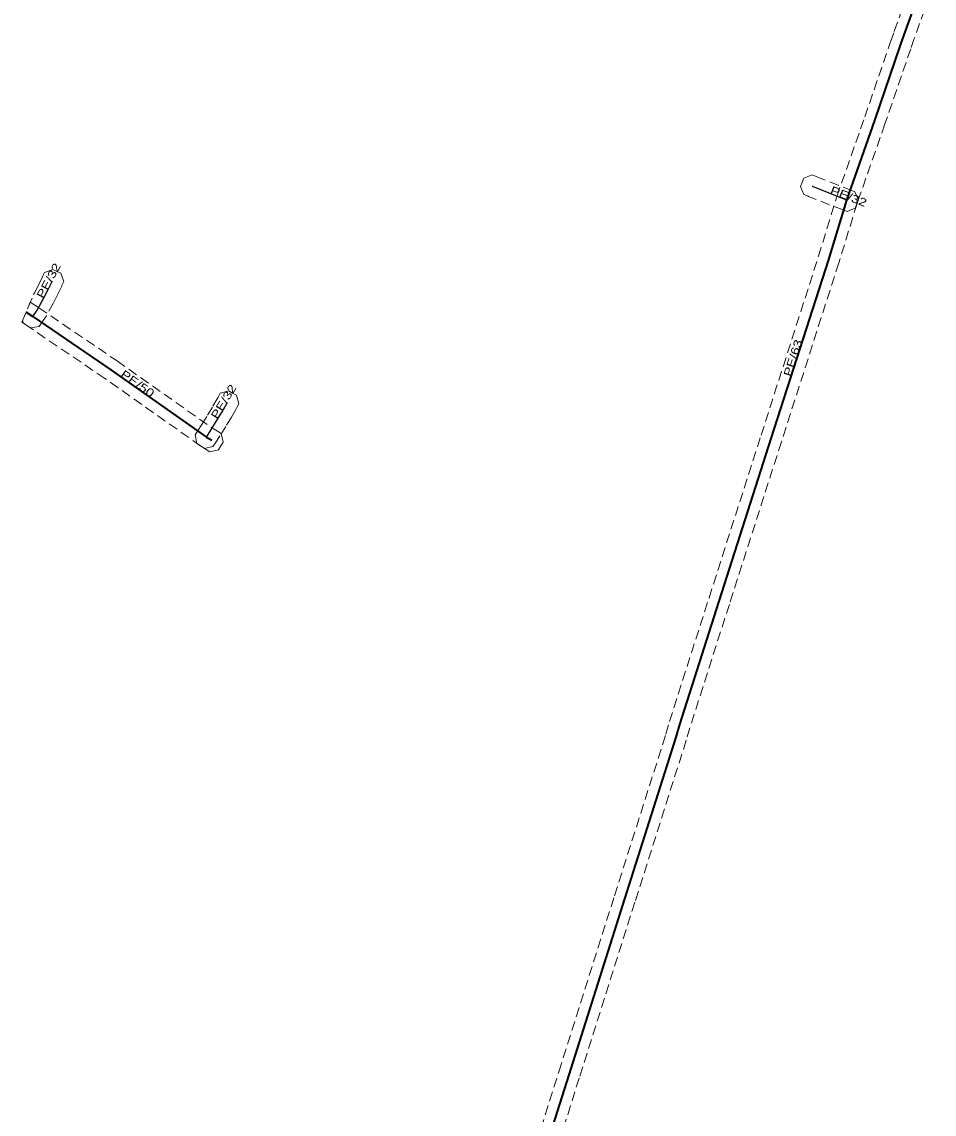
# Model space of a CAD drawing. Extents: x -601345 to -601001, y -1004225 to -1003815.
# Drawn here: x -601277.1 to -601191.6, y -1004020.2 to -1003917.9 of the extents above; entities that cross this region are included whole.
import ezdxf

# ---------------------------------------------------------------- set-up
doc = ezdxf.new("R2010")
doc.units = 0
doc.header["$LTSCALE"] = 0.3
doc.linetypes.add('MEDIUM_DASHED', pattern=[4.5, 3, -1.5])
doc.layers.add('1', color=7, linetype='MEDIUM_DASHED', lineweight=13)
doc.layers.add('24', color=7, linetype='Continuous', lineweight=25)
doc.layers.add('30', color=7, linetype='Continuous')

msp = doc.modelspace()

# ---------------------------------------------------------------- linework, layer by layer
at = {"layer": '1'}
for points in [[(-601228.474, -1004021.588), (-601226.804, -1004016.26), (-601221.583, -1003999.768), (-601216.777, -1003984.62), (-601216.437, -1003983.439), (-601212.732, -1003971.845), (-601207.852, -1003956.605), (-601202.474, -1003939.831), (-601200.76, -1003934.247), (-601198.135, -1003926.773), (-601195.725, -1003919.723), (-601195.383, -1003918.746), (-601193.522, -1003913.534)], [(-601191.638, -1003914.206), (-601193.497, -1003919.414), (-601193.835, -1003920.377), (-601196.245, -1003927.427), (-601198.86, -1003934.873), (-601200.566, -1003940.429), (-601205.948, -1003957.215), (-601210.828, -1003972.455), (-601214.523, -1003984.021), (-601214.863, -1003985.2), (-601219.677, -1004000.372), (-601224.896, -1004016.86), (-601226.606, -1004022.312)]]:
    msp.add_lwpolyline(points, dxfattribs=at)
for points in [[(-601199.789, -1003935.642), (-601200.175, -1003935.491), (-601203.422, -1003934.218), (-601203.451, -1003934.207), (-601203.834, -1003934.05), (-601204.155, -1003933.286), (-601203.998, -1003932.902), (-601203.841, -1003932.519), (-601203.077, -1003932.198), (-601202.693, -1003932.355), (-601202.678, -1003932.362), (-601199.445, -1003933.629), (-601199.059, -1003933.78), (-601198.728, -1003934.539), (-601198.879, -1003934.925), (-601199.03, -1003935.311)], [(-601276.998, -1003946.079), (-601277.043, -1003945.837), (-601276.017, -1003943.416), (-601275.934, -1003943.262), (-601275.564, -1003942.552), (-601275.183, -1003941.76), (-601275.167, -1003941.727), (-601274.99, -1003941.353), (-601274.21, -1003941.073), (-601273.836, -1003941.25), (-601273.462, -1003941.427), (-601273.182, -1003942.207), (-601273.359, -1003942.581), (-601273.377, -1003942.62), (-601273.776, -1003943.448), (-601274.166, -1003944.198), (-601274.816, -1003945.402), (-601275.266, -1003946.057), (-601275.501, -1003946.398), (-601276.316, -1003946.549), (-601276.657, -1003946.314)], [(-601276.646, -1003946.321), (-601277.117, -1003946.011), (-601276.323, -1003944.139), (-601275.534, -1003944.659), (-601268.201, -1003949.638), (-601259.268, -1003955.936), (-601258.793, -1003956.23), (-601258.441, -1003956.448), (-601258.252, -1003957.255), (-601258.47, -1003957.607), (-601258.688, -1003957.959), (-601259.495, -1003958.148), (-601259.847, -1003957.93), (-601260.372, -1003957.604), (-601269.339, -1003951.282)], [(-601260.884, -1003956.572), (-601260.658, -1003956.225), (-601260.257, -1003955.608), (-601259.724, -1003954.73), (-601259.212, -1003953.893), (-601258.821, -1003953.199), (-601258.727, -1003953.032), (-601258.524, -1003952.671), (-601257.726, -1003952.449), (-601257.365, -1003952.652), (-601257.004, -1003952.855), (-601256.782, -1003953.653), (-601256.985, -1003954.014), (-601257.079, -1003954.181), (-601257.488, -1003954.907), (-601258.016, -1003955.77), (-601258.563, -1003956.672), (-601258.982, -1003957.315), (-601259.208, -1003957.663), (-601260.018, -1003957.834), (-601260.365, -1003957.608), (-601260.713, -1003957.382)]]:
    msp.add_lwpolyline(points, close=True, dxfattribs=at)
at = {"layer": '24', "lineweight": 40}
for points in [[(-601227.54, -1004021.95), (-601225.85, -1004016.56), (-601220.63, -1004000.07), (-601215.82, -1003984.91), (-601215.48, -1003983.73), (-601211.78, -1003972.15), (-601206.9, -1003956.91), (-601201.52, -1003940.13), (-601199.81, -1003934.56), (-601197.19, -1003927.1), (-601194.78, -1003920.05), (-601194.44, -1003919.08), (-601192.58, -1003913.87)], [(-601276.72, -1003945.075), (-601276.09, -1003945.49), (-601268.77, -1003950.46), (-601259.82, -1003956.77), (-601259.32, -1003957.08)]]:
    msp.add_lwpolyline(points, dxfattribs=at)
at = {"layer": '24'}
for points in [[(-601199.81, -1003934.56), (-601203.05, -1003933.29), (-601203.072, -1003933.281)], [(-601276.09, -1003945.49), (-601275.67, -1003944.88), (-601275.05, -1003943.73), (-601274.67, -1003943), (-601274.28, -1003942.19), (-601274.263, -1003942.154)], [(-601259.82, -1003956.77), (-601259.41, -1003956.14), (-601258.87, -1003955.25), (-601258.35, -1003954.4), (-601257.95, -1003953.69), (-601257.856, -1003953.523)]]:
    msp.add_lwpolyline(points, dxfattribs=at)

# ---------------------------------------------------------------- texts
at = {"layer": '30', "width": 1.3}
for s, rotation, p in [('PE/32', 338.596, (-601201.441, -1003933.92)), ('PE/32', 61.67, (-601275.118, -1003943.855)), ('PE/63', 72.223, (-601205.058, -1003951.165)), ('PE/50', 324.815, (-601267.937, -1003951.047)), ('PE/32', 58.543, (-601258.815, -1003955.16))]:
    msp.add_text(s, height=0.75, rotation=rotation, dxfattribs=at).set_placement(p)

doc.saveas('drawing.dxf')
